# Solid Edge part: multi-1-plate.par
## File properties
Author: CADCIM
Template: iso part.par
Last saved by: Cadcim
Revision: 2
Application: Solid Edge
Accuracy: 0.990
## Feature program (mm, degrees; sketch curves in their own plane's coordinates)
base feature "unnamed BaseFeature 1"
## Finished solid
Body 1: solid body, 10 faces, 24 edges, 16 vertices.
  Faces by surface: plane 6, cylinder 4
  Edges by curve: line 16, circle 8
Bounding box of the edges (mm): 352.904 x 180.000 x 25.000, from (-174.5092, -90, -25) to (178.3947, 90, 0).
Cylindrical faces by radius (mm): R32.5698 x1, R35.0943 x1, R90 x2
Planar faces by outward normal: +z 1, -z 1, oblique 4
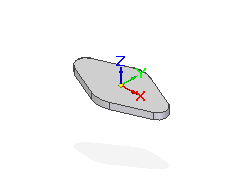
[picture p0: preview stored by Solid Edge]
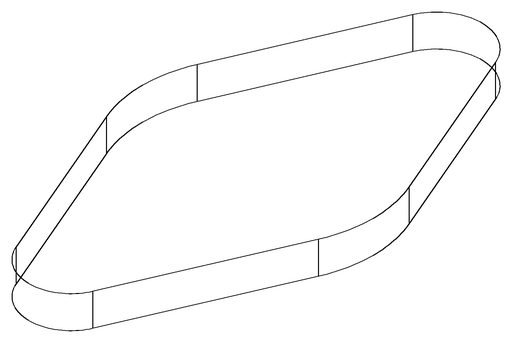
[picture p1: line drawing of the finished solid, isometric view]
